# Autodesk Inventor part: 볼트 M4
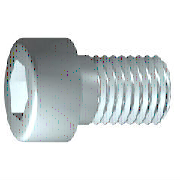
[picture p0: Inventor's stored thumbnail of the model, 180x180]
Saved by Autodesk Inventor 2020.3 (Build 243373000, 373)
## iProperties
IsCustomPart: 0
Created: 2012-02
Part Number: 볼트 M4
Material: 스테인리스강
Description: 6각 소켓 머리 캡 나사
Document SubType Name: Modeling
Standard: ISO 4762
Designer: mduedu
Standard Revision: Fourth edition 2004-03-01
Standards Organization: ISO
Language: ko-KR
Size Designation: M4 x 12
Categories: <MemberInstance><Categories><Category DisplayName="조임쇠" InternalName="e4da775c-781d-43d5-af7c-5136215cf5a6" Mnemonic="FSTN"><Category DisplayName="볼트" InternalN
Density: 8.08 g/cm^3
Appearance: 반광택
Author: mduedu
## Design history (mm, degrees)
sketch "스케치1"
  geometry: L1 (-1, 0)-(12, 0); L2 (12, 0)-(12, 2); L3 (12, 2)-(1.75, 2); L4 (1.75, 2)-(1.32, 2); L5 (1.32, 2)-(0, 2); L6 (0, 2)-(0, 3.5); L7 (0, 3.5)-(-4, 3.5); L8 (-4, 3.5)-(-4, 1.732); L9 (-4, 1.732)-(-2, 1.732); L10 (-2, 1.732)-(-1, 0); L11 (-7.2, 0)-(15.2, 0) reference; L12 (0, -0.7)-(0, 4.2) reference; L13 (1.75, 2)-(0, 2)
  constraints: 22 end point, 6 parallel, 2 collinear, 2 perpendicular, 1 horizontal, 1 point on line
  dimensions: "d1" = 10.25 distance from line of L3.end L2 (= GEL); "d2" = 0.42952 distance of L4.end L3.end (computed from GAL); "d3" = 4 distance between parallel lines of L8 L6 (= KOH); "d4" = 2 distance of L8.end L9.end (= INTI); "d5" = 60 deg angle of L10 L1; "d6" = 4 diameter of L3 L1 (= GD); "d7" = 4 diameter of L5 L1 (= BDM); "d8" = 3.4641 diameter of L9 L1 (= 1.1547 x SW); "d9" = 7 diameter of L7 L1 (= KOD); "d26" = 12 distance between parallel lines of L12 L2 (= NLG)
revolve "본체" sketch "스케치1" stored, may be unused: angle "d10" = 90 deg
sketch "스케치2"
  geometry: L1 (0, -4.9)-(0, 4.9) reference; L2 (-4.9, 0)-(4.9, 0) reference; L3 (1.732, 0)-(0.866, -1.5); L4 (0.866, -1.5)-(-0.866, -1.5); L5 (-0.866, -1.5)-(-1.732, 0); L6 (-1.732, 0)-(-0.866, 1.5); L7 (-0.866, 1.5)-(0.866, 1.5); L8 (0.866, 1.5)-(1.732, 0); 2 further points
  constraints: 12 end point, 1 coincident, 1 horizontal alignment, 1 point on line, 12 other
extrude "슬롯" join sketch "스케치2" stored distance "d11" = 10; taper "d12" = 0 deg
workplane "Work Plane1"
fillet "Fillet2" dims "d30" = 0.1 (= R)
body "Solid1"
fillet "모깎기1" dims "d17" = 0.4 (= RR)
feature "스레드" dims "d13" = 10.25 (= GEL), "d14" = 0
chamfer "모따기1" distance "d15" = 0.42941 (= -0.5 x SPD + 0.5 x GD); stored, may be unused: second distance "d16" = 0.42941 (= GUL), angle "d27" = 45 deg
other parameters: "GD" = 4 [user parameter; used in 2 equation terms], "NLG" = 12 [user parameter; used in 1 equation term], "GEL" = 10.25 [user parameter; used in 2 equation terms], "KOD" = 7 [user parameter; used in 1 equation term], "KOH" = 4 [user parameter; used in 1 equation term], "INTI" = 2 [user parameter; used in 1 equation term], "GAL" = 0.42941 (= 0.61345 x PTC) [user parameter; used in 1 equation term], "GUL" = 0.42941 (= 0.61345 x PTC) [user parameter; used in 1 equation term], "BDM" = 4 (= NND) [user parameter; used in 1 equation term], "SW" = 3 [user parameter; used in 2 equation terms], "RR" = 0.4 [user parameter; used in 1 equation term], "SPD" = 3.14117 (= NND - 1.2269 x PTC) [user parameter; used in 1 equation term], "d19" = 0, "d28" = 0, "d29" = 0, "R" = 0.1 [user parameter; used in 1 equation term], "TOA" = 30 deg [user parameter], "GD1" = 3.14117 (= THREADDIA - 1.2269 x PTC) [user parameter], "THREADDIA" = 4 [user parameter; used in 1 equation term], "FAWI" = 45 deg [user parameter], "TPU" = 14.28571 (computed from PTC) [user parameter], "PTC" = 0.7 [user parameter; used in 5 equation terms], "NND" = 4 [user parameter; used in 2 equation terms], "E0" = 3.465 (= 1.155 x SW) [user parameter]
